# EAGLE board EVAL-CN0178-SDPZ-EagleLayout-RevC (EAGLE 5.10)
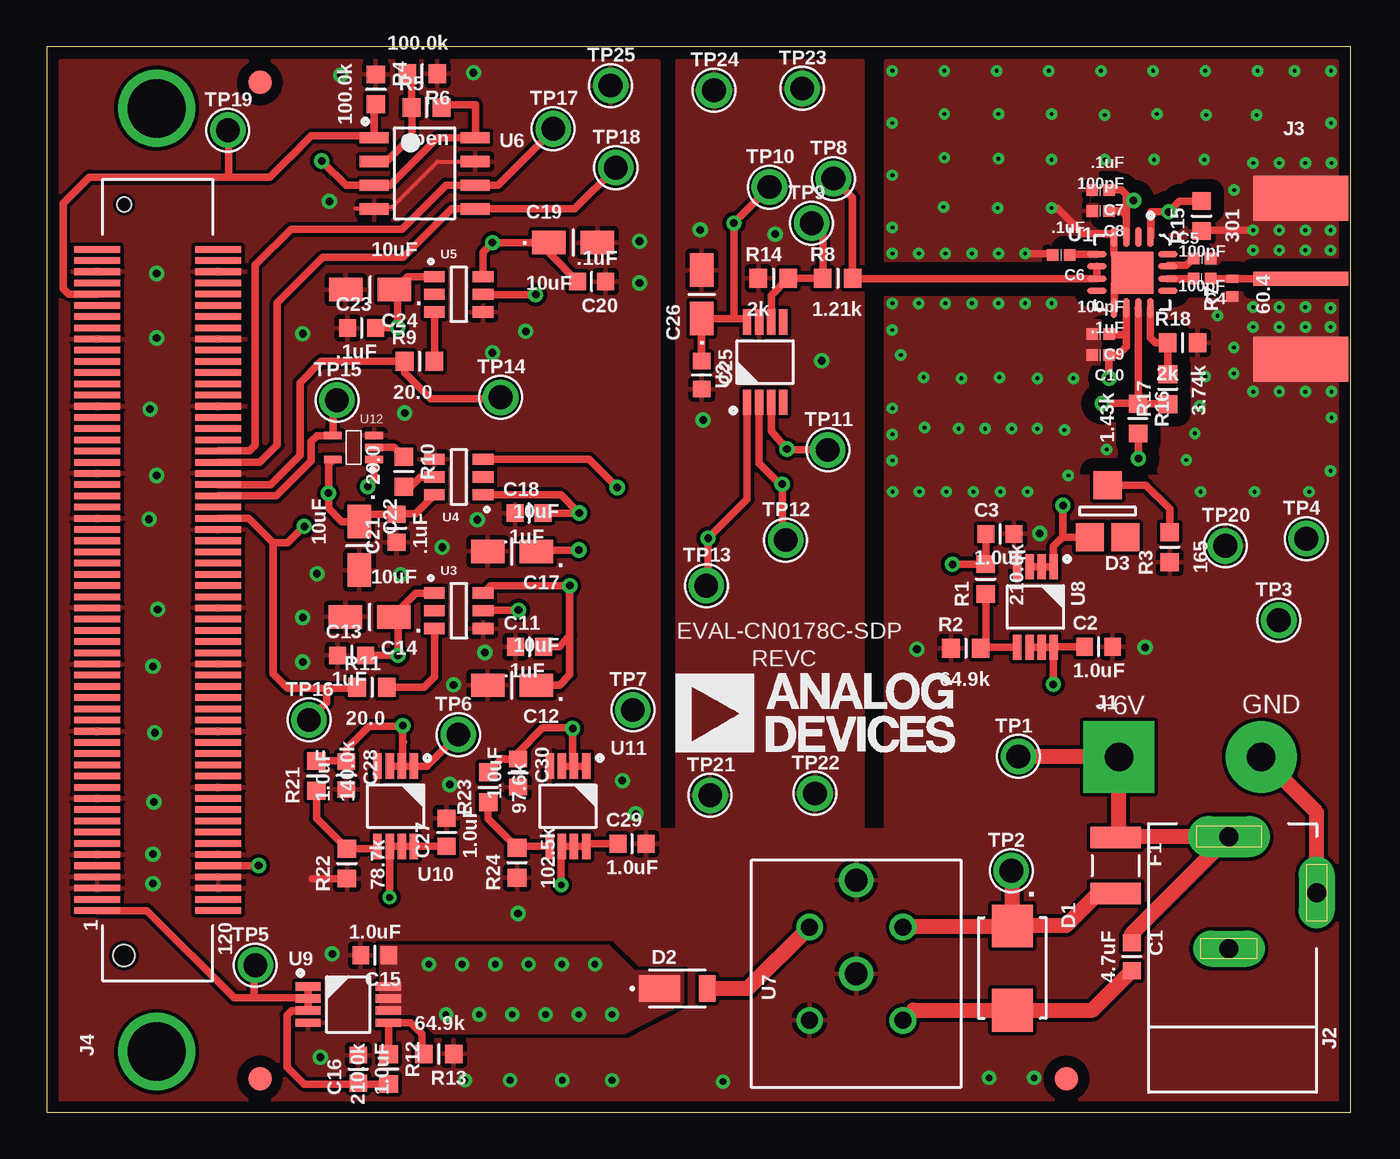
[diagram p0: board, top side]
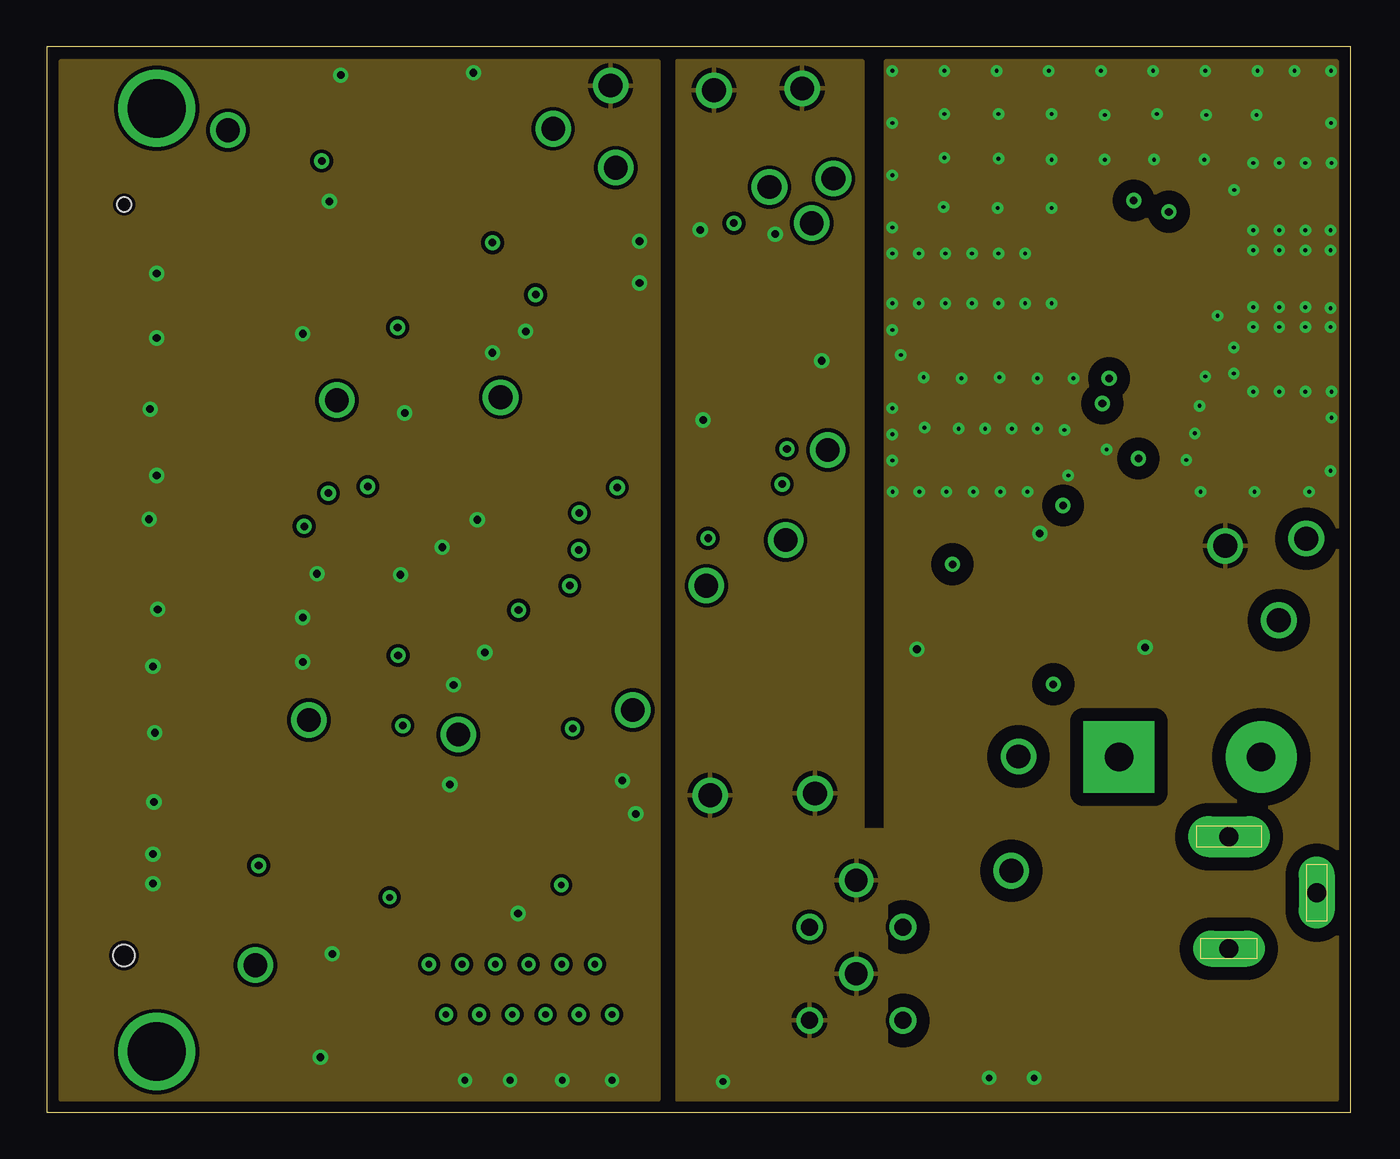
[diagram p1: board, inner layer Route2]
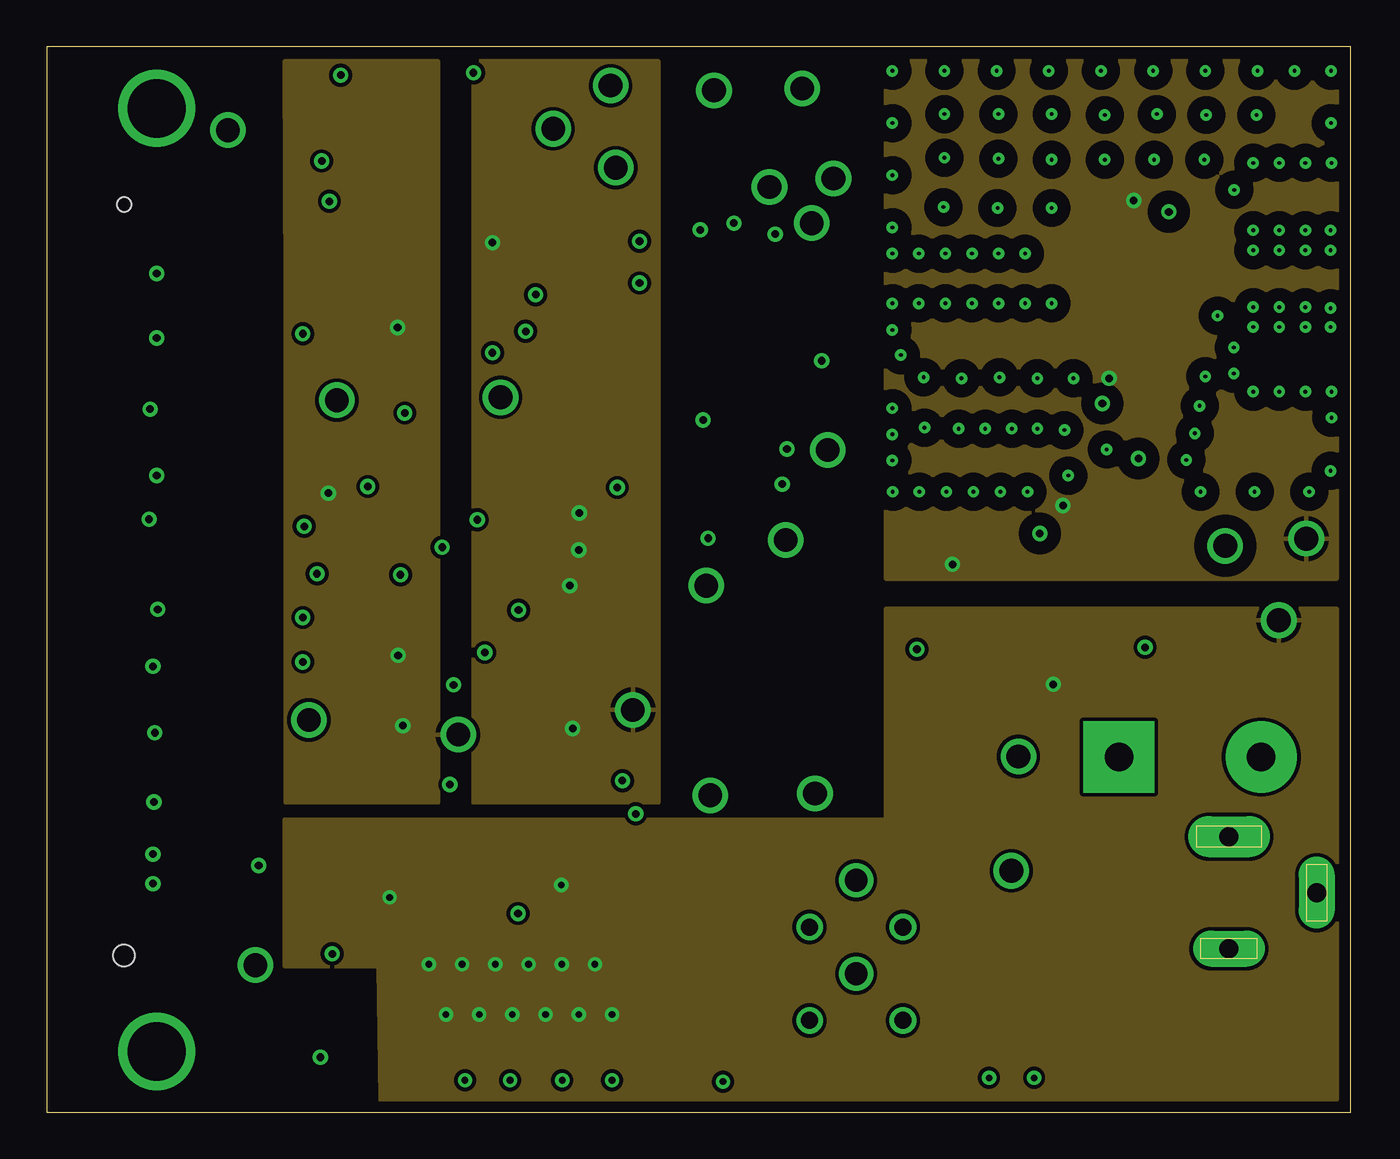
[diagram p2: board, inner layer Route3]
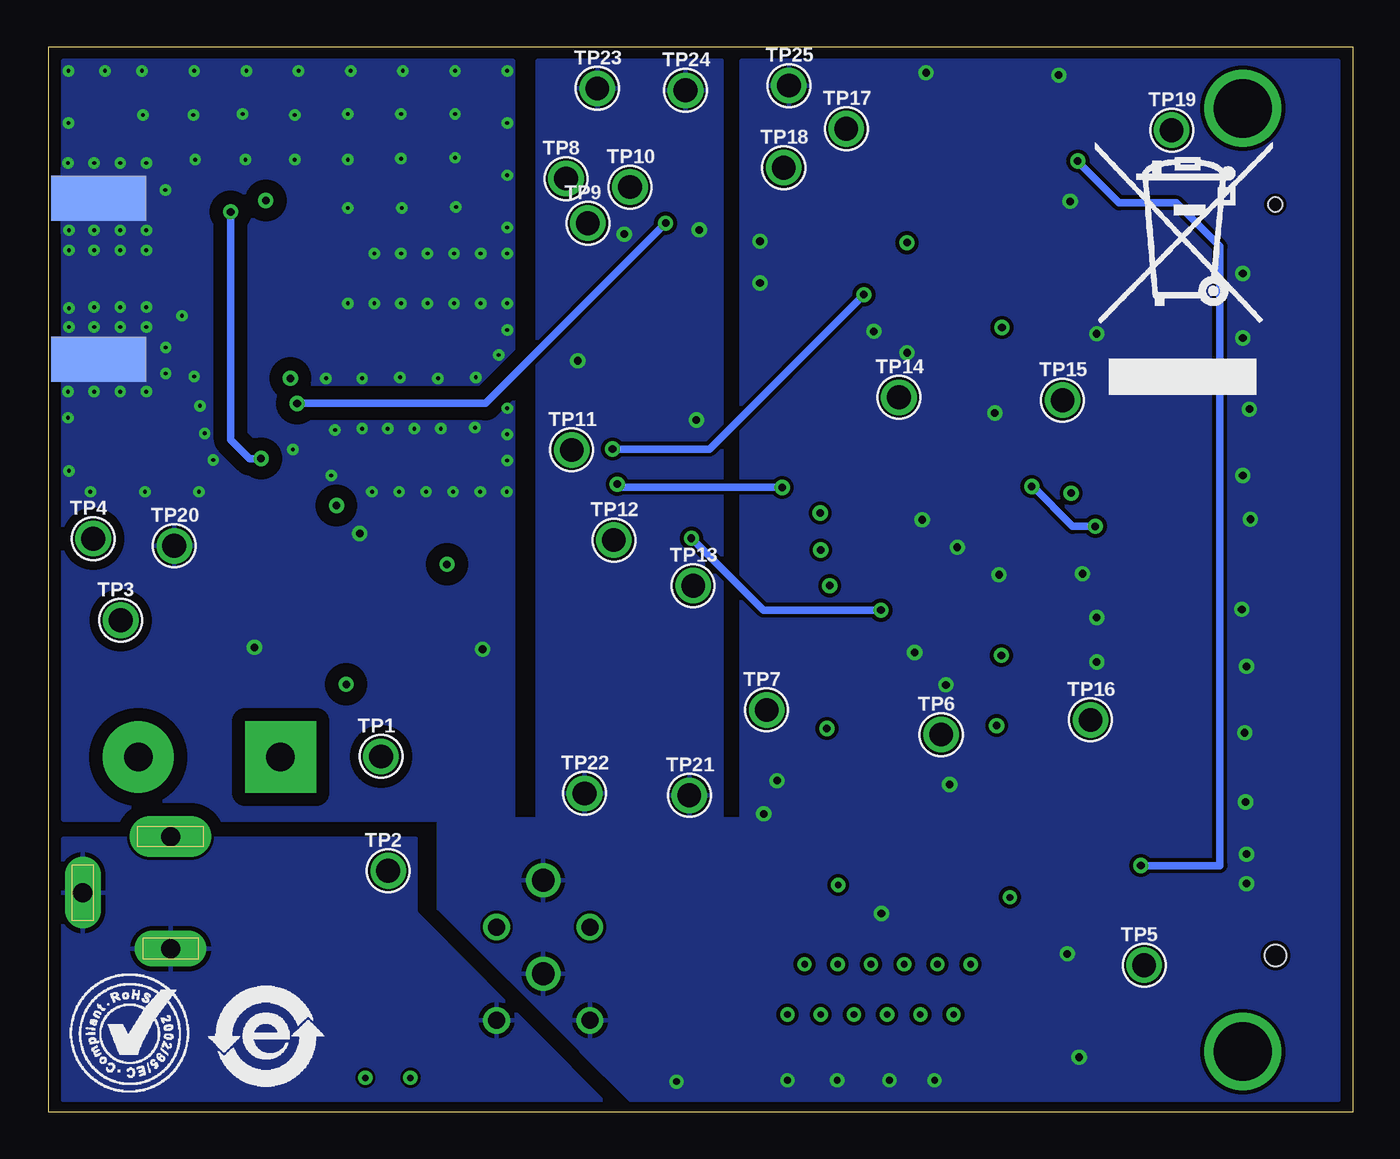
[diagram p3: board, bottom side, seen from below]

Size 69.85 x 57.05 mm. Coordinates in mm from the lower left corner, seen from the top.
Outline: 0,0 69.85,0 69.85,57.05 0,57.05 0,0
Copper layers (1+2*3+16): Top 0.035mm / dielectric 0.36mm / Route2 0.035mm / dielectric 0.71mm / Route3 0.035mm / dielectric 0.36mm / Bottom 0.035mm
Design rules "default *": minimum track width 5mil, minimum drill 8mil, track to track 6mil, track to pad 6mil, pad to pad 6mil, via to via 6mil, smd to smd 6mil, copper to edge 0mil, drill to drill 8mil, minimum pad ring 10mil, minimum via ring 8mil, stop-mask expansion 2mil, vias tented up to drill 0mil, thermal gap 10mil

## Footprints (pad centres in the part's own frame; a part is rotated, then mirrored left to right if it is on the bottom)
C_CAPC1608X55N = smd 0.9 x 0.95: 1 -0.75,0; 2 0.75,0
C_CAPC1005X55N = smd 0.62 x 0.62: 1 -0.45,0; 2 0.45,0
C_CAPMP3216X180N = smd 1.8 x 1.25: 1 -1.3,0; 2 1.3,0
D_DIOM5436X241N = smd 2.3 x 2.2: A 2.25,0; K -2.25,0
D_POWER123 = smd 0.9 x 1.4: A 1.6,0 | smd 2.2 x 1.4: K -0.95,0
D_LED_LUMEX_SMD = smd 1.5 x 1.5: 1 -0.95,1.4; 2 0.95,1.4; 3 0,-1.4
C_CAPC3225X94N = smd 1.15 x 2.7: 1 -1.5,0; 2 1.5,0
ID_PICKNPLACE = smd 1.27 x 1.27: P$1 0,0
CON_HEADER_2PIN = drill 1.524 pad 3.81 square: 1 -3.81,0 | drill 1.524 pad 3.81 round: 2 3.81,0
CON_BARREL_JACK = drill 1.016 pad 2.184 long: 1 -3,0 | drill 1.016 pad 1.93 long: 2 3,0; 3 0,4.7
CON_COAX_SMD = smd 2.413 x 5.08: PAD1 -4.318,-2.54; PAD2 4.318,-2.54 | smd 2.413 x 5.08 bottom: PAD3 -4.318,-2.54; PAD4 4.318,-2.54 | smd 0.762 x 5.08: SIG 0,-2.54
CON_120PIN_SMD = smd 0.35 x 2.46: 1 -17.7,3.23; 2 -17.1,3.23; 3 -16.5,3.23; 4 -15.9,3.23; 5 -15.3,3.23; 6 -14.7,3.23; 7 -14.1,3.23; 8 -13.5,3.23; 9 -12.9,3.23; 10 -12.3,3.23; 11 -11.7,3.23; 12 -11.1,3.23; 13 -10.5,3.23; 14 -9.9,3.23; 15 -9.3,3.23; 16 -8.7,3.23; 17 -8.1,3.23; 18 -7.5,3.23; 19 -6.9,3.23; 20 -6.3,3.23; 21 -5.7,3.23; 22 -5.1,3.23; 23 -4.5,3.23; 24 -3.9,3.23; 25 -3.3,3.23; 26 -2.7,3.23; 27 -2.1,3.23; 28 -1.5,3.23; 29 -0.9,3.23; 30 -0.3,3.23; 31 0.3,3.23; 32 0.9,3.23; 33 1.5,3.23; 34 2.1,3.23; 35 2.7,3.23; 36 3.3,3.23; 37 3.9,3.23; 38 4.5,3.23; 39 5.1,3.23; 40 5.7,3.23; 41 6.3,3.23; 42 6.9,3.23; 43 7.5,3.23; 44 8.1,3.23; 45 8.7,3.23; 46 9.3,3.23; 47 9.9,3.23; 48 10.5,3.23; 49 11.1,3.23; 50 11.7,3.23; 51 12.3,3.23; 52 12.9,3.23; 53 13.5,3.23; 54 14.1,3.23; 55 14.7,3.23; 56 15.3,3.23; 57 15.9,3.23; 58 16.5,3.23; 59 17.1,3.23; 60 17.7,3.23; 61 17.7,-3.23; 62 17.1,-3.23; 63 16.5,-3.23; 64 15.9,-3.23; 65 15.3,-3.23; 66 14.7,-3.23; 67 14.1,-3.23; 68 13.5,-3.23; 69 12.9,-3.23; 70 12.3,-3.23; 71 11.7,-3.23; 72 11.1,-3.23; 73 10.5,-3.23; 74 9.9,-3.23; 75 9.3,-3.23; 76 8.7,-3.23; 77 8.1,-3.23; 78 7.5,-3.23; 79 6.9,-3.23; 80 6.3,-3.23; 81 5.7,-3.23; 82 5.1,-3.23; 83 4.5,-3.23; 84 3.9,-3.23; 85 3.3,-3.23; 86 2.7,-3.23; 87 2.1,-3.23; 88 1.5,-3.23; 89 0.9,-3.23; 90 0.3,-3.23; 91 -0.3,-3.23; 92 -0.9,-3.23; 93 -1.5,-3.23; 94 -2.1,-3.23; 95 -2.7,-3.23; 96 -3.3,-3.23; 97 -3.9,-3.23; 98 -4.5,-3.23; 99 -5.1,-3.23; 100 -5.7,-3.23; 101 -6.3,-3.23; 102 -6.9,-3.23; 103 -7.5,-3.23; 104 -8.1,-3.23; 105 -8.7,-3.23; 106 -9.3,-3.23; 107 -9.9,-3.23; 108 -10.5,-3.23; 109 -11.1,-3.23; 110 -11.7,-3.23; 111 -12.3,-3.23; 112 -12.9,-3.23; 113 -13.5,-3.23; 114 -14.1,-3.23; 115 -14.7,-3.23; 116 -15.3,-3.23; 117 -15.9,-3.23; 118 -16.5,-3.23; 119 -17.1,-3.23; 120 -17.7,-3.23 | drill 3.124 round: MH1 -25.25,0.05; MH2 25.25,0.05 | hole 0.762: 20.1,1.8 | hole 1.168: -20.1,1.8
R_RESC1608X50AN = smd 0.95 x 1: 1 -0.8,0; 2 0.8,0
R_RESC1005X40N_RF = smd 0.57 x 0.62: 1 -0.48,0 | smd 0.406 x 0.62: 2 0.48,0
TP_50MIL = drill 1.27 round: 1 0,0
IC_QFN65P400X400X100-17VN = smd 1.05 x 0.35: 1 -1.9,0.975; 2 -1.9,0.325; 3 -1.9,-0.325; 4 -1.9,-0.975; 9 1.9,-0.975; 10 1.9,-0.325; 11 1.9,0.325; 12 1.9,0.975 | smd 0.35 x 1.05: 5 -0.975,-1.9; 6 -0.325,-1.9; 7 0.325,-1.9; 8 0.975,-1.9; 13 0.975,1.9; 14 0.325,1.9; 15 -0.325,1.9; 16 -0.975,1.9 | smd 2.25 x 2.25: 17 0,0
IC_SOP65P490X94-8N = smd 1.35 x 0.45: 1 -2.15,0.975; 2 -2.15,0.325; 3 -2.15,-0.325; 4 -2.15,-0.975; 5 2.15,-0.975; 6 2.15,-0.325; 7 2.15,0.325; 8 2.15,0.975
IC_SOT95P280X145-6AN = smd 1.1 x 0.6: 1 -1.3,0.95; 2 -1.3,0; 3 -1.3,-0.95; 4 1.3,-0.95; 5 1.3,0; 6 1.3,0.95
IC_SOIC127P600X175-8N = smd 1.55 x 0.6: 1 -2.7,1.905; 2 -2.7,0.635; 3 -2.7,-0.635; 4 -2.7,-1.905; 5 2.7,-1.905; 6 2.7,-0.635; 7 2.7,0.635; 8 2.7,1.905
IC_BNX016-01 = drill 0.914 round: 1 2.5,-2.5; 2 2.5,2.5; 3 -2.5,-2.5; 4 -2.5,2.5 | drill 1.219 round: 5 0,0; 6 5,0
IC_SOT65P210X110-5N = smd 0.95 x 0.4: 1 -1.1,0.65; 2 -1.1,0; 3 -1.1,-0.65; 4 1.1,-0.65; 5 1.1,0.65

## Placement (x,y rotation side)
C1  4.7uF  [C_CAPC1608X55N]  58.12,8.33 270 top
C2  1.0uF  [C_CAPC1608X55N]  56.34,24.92 0 top
C3  1.0uF  [C_CAPC1608X55N]  51.05,30.96 0 top
C4  100pF  [C_CAPC1005X55N]  61.87,44.63 180 top
C5  100pF  [C_CAPC1005X55N]  61.87,45.72 0 top
C6  .1uF  [C_CAPC1005X55N]  54.33,45.9 180 top
C7  .1uF  [C_CAPC1005X55N]  56.44,49.38 180 top
C8  100pF  [C_CAPC1005X55N]  56.44,48.26 180 top
C9  100pF  [C_CAPC1005X55N]  56.44,41.66 180 top
C10  .1uF  [C_CAPC1005X55N]  56.44,40.54 180 top
C11  .1uF  [C_CAPC1608X55N]  25.86,24.92 0 top
C12  10uF  [C_CAPMP3216X180N]  24.92,22.86 180 top
C13  .1uF  [C_CAPC1608X55N]  16.33,24.46 0 top
C14  10uF  [C_CAPMP3216X180N]  17.3,26.52 180 top
C15  1.0uF  [C_CAPC1608X55N]  17.58,8.41 180 top
C16  1.0uF  [C_CAPC1608X55N]  16.69,2.31 90 top
C17  10uF  [C_CAPMP3216X180N]  24.92,30.02 180 top
C18  .1uF  [C_CAPC1608X55N]  25.83,32.08 0 top
C19  10uF  [C_CAPMP3216X180N]  28.19,46.56 0 top
C20  .1uF  [C_CAPC1608X55N]  29.18,44.48 180 top
C21  .1uF  [C_CAPC1608X55N]  18.75,31.27 90 top
C22  10uF  [C_CAPMP3216X180N]  16.74,30.33 270 top
C23  .1uF  [C_CAPC1608X55N]  16.87,41.99 0 top
C24  10uF  [C_CAPMP3216X180N]  17.32,44.04 180 top
C25  [C_CAPC1608X55N]  35.08,39.47 270 top
C26  10uF  [C_CAPMP3216X180N]  35.08,43.79 90 top
C27  1.0uF  [C_CAPC1608X55N]  21.41,14.99 90 top
C28  1.0uF  [C_CAPC1608X55N]  16.05,18.03 270 top
C29  1.0uF  [C_CAPC1608X55N]  31.34,14.38 0 top
C30  1.0uF  [C_CAPC1608X55N]  25.25,18.16 270 top
D1  [D_DIOM5436X241N]  51.71,7.72 270 top
D2  [D_POWER123]  33.78,6.63 0 top
D3  [D_LED_LUMEX_SMD]  56.82,32.18 180 top
DRILEGEND  [DRILEGEND]  not placed on the board
F1  [C_CAPC3225X94N]  57.25,13.21 270 top
ID1  INDICATOR  [ID_PICKNPLACE]  11.43,55.14 0 top
ID2  INDICATOR  [ID_PICKNPLACE]  54.61,1.8 0 top
ID3  INDICATOR  [ID_PICKNPLACE]  11.43,1.8 0 top
J1  CON_HEADER_2PIN  [CON_HEADER_2PIN]  61.24,19.02 0 top
J2  [CON_BARREL_JACK]  63.32,11.76 270 top
J3  [CON_COAX_SMD]  64.62,44.63 90 top
J4  [CON_120PIN_SMD]  5.94,28.5 90 top
R1  210.0k  [R_RESC1608X50AN]  50.29,28.55 90 top
R2  64.9k  [R_RESC1608X50AN]  49.23,24.84 0 top
R3  165  [R_RESC1608X50AN]  60.15,30.25 90 top
R4  100.0k  [R_RESC1608X50AN]  17.63,54.76 270 top
R5  open  [R_RESC1608X50AN]  20.35,53.8 0 top
R6  100.0k  [R_RESC1608X50AN]  20.12,55.6 180 top
R7  60.4  [R_RESC1005X40N_RF]  63.5,44.15 90 top
R8  1.21k  [R_RESC1608X50AN]  42.37,44.65 0 top
R9  20.0  [R_RESC1608X50AN]  19.96,40.21 0 top
R10  20.0  [R_RESC1608X50AN]  19.13,34.29 270 top
R11  20.0  [R_RESC1608X50AN]  17.42,22.76 0 top
R12  210.0k  [R_RESC1608X50AN]  18.31,2.31 270 top
R13  64.9k  [R_RESC1608X50AN]  21.01,3.12 180 top
R14  2k  [R_RESC1608X50AN]  38.91,44.65 0 top
R15  301  [R_RESC1608X50AN]  61.85,47.98 90 top
R16  1.43k  [R_RESC1608X50AN]  58.45,37.13 270 top
R17  3.74k  [R_RESC1608X50AN]  60.05,38.71 90 top
R18  2k  [R_RESC1608X50AN]  60.83,41.2 0 top
R21  140.0k  [R_RESC1608X50AN]  14.45,18.01 90 top
R22  78.7k  [R_RESC1608X50AN]  16.08,13.31 90 top
R23  97.6k  [R_RESC1608X50AN]  23.65,17.4 90 top
R24  102.5k  [R_RESC1608X50AN]  25.2,13.36 90 top
TP1  TESTPOINT_50MIL  [TP_50MIL]  52.04,19.05 0 top
TP2  TESTPOINT_50MIL  [TP_50MIL]  51.66,12.93 0 top
TP3  TESTPOINT_50MIL  [TP_50MIL]  65.99,26.34 0 top
TP4  TESTPOINT_50MIL  [TP_50MIL]  67.46,30.71 0 top
TP5  TESTPOINT_50MIL  [TP_50MIL]  11.18,7.87 0 top
TP6  TESTPOINT_50MIL  [TP_50MIL]  22.05,20.22 0 top
TP7  TESTPOINT_50MIL  [TP_50MIL]  31.39,21.54 0 top
TP8  TESTPOINT_50MIL  [TP_50MIL]  42.14,49.99 0 top
TP9  TESTPOINT_50MIL  [TP_50MIL]  40.97,47.6 0 top
TP10  TESTPOINT_50MIL  [TP_50MIL]  38.71,49.53 0 top
TP11  TESTPOINT_50MIL  [TP_50MIL]  41.83,35.46 0 top
TP12  TESTPOINT_50MIL  [TP_50MIL]  39.57,30.63 0 top
TP13  TESTPOINT_50MIL  [TP_50MIL]  35.33,28.19 0 top
TP14  TESTPOINT_50MIL  [TP_50MIL]  24.31,38.28 0 top
TP15  TESTPOINT_50MIL  [TP_50MIL]  15.54,38.13 0 top
TP16  TESTPOINT_50MIL  [TP_50MIL]  14.05,21.01 0 top
TP17  TESTPOINT_50MIL  [TP_50MIL]  27.13,52.65 0 top
TP18  TESTPOINT_50MIL  [TP_50MIL]  30.48,50.57 0 top
TP19  TESTPOINT_50MIL  [TP_50MIL]  9.7,52.58 0 top
TP20  TESTPOINT_50MIL  [TP_50MIL]  63.12,30.33 0 top
TP21  TESTPOINT_50MIL  [TP_50MIL]  35.53,16.97 0 top
TP22  TESTPOINT_50MIL  [TP_50MIL]  41.15,17.07 0 top
TP23  TESTPOINT_50MIL  [TP_50MIL]  40.46,54.81 0 top
TP24  TESTPOINT_50MIL  [TP_50MIL]  35.74,54.71 0 top
TP25  TESTPOINT_50MIL  [TP_50MIL]  30.2,54.97 0 top
U1  IC_ADL5902_LFCSP_VQ  [IC_QFN65P400X400X100-17VN]  58.14,44.96 270 top
U2  IC_AD7466_TSSOP8  [IC_SOP65P490X94-8N]  38.48,40.16 90 top
U3  [IC_SOT95P280X145-6AN]  22.07,26.85 0 top
U4  [IC_SOT95P280X145-6AN]  22.07,34.01 180 top
U5  [IC_SOT95P280X145-6AN]  22.07,43.79 0 top
U6  [IC_SOIC127P600X175-8N]  20.24,50.27 0 top
U7  [IC_BNX016-01]  43.36,7.42 90 top
U8  [IC_SOP65P490X94-8N]  52.96,27.05 270 top
U9  [IC_SOP65P490X94-8N]  16.15,5.77 0 top
U10  [IC_SOP65P490X94-8N]  18.69,16.38 270 top
U11  [IC_SOP65P490X94-8N]  27.91,16.38 270 top
U12  IC_74HC_HCT1G125  [IC_SOT65P210X110-5N]  16.43,35.59 180 top
U$11  [LOGO_ANALOG_DEVICES]  33.68,19.25 0 top
U$12  [LOGO_ROHS]  68.83,1.07 0 bottom
U$13  [LOGO_ROHS_CHINA]  61.52,1.37 0 bottom
U$14  [LOGO_WEEE_TRASH]  13.82,38.4 0 bottom

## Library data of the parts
C1-C25 C27-C30 D1-D3 F1 J1-J4 R1-R18 R21-R24 TP1-TP25 U1-U12 = CN-0178-RevC
C26 = CN-0178-RevB
DRILEGEND = drilegend
ID1-ID3 = CN0150
U$11-U$14 = Templates

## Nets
+2.3V: C11.2 C12.1 C17.1 C18.2 C19.1 C20.2 C30.1 R23.2 TP7.1 U3.6 U4.1 U5.6 U11.1 U11.2 U11.3
+3.3V: C13.2 C14.1 C21.2 C22.1 C23.2 C24.1 C28.1 R21.2 TP6.1 U3.1 U4.6 U5.1 U10.1 U10.2 U10.3 U12.5
+3.3V_EEPROM: J4.116 R5.2 U6.3 U6.8
+5V_ANALOG: C3.1 C7.1 C8.1 C9.1 C10.1 D3.2 R1.2 TP4.1 U1.3 U1.10 U8.1 U8.2 U8.3
+5V_SDP: C16.1 J4.1 R12.2 TP5.1 U9.1 U9.2 U9.3
GND: C2.2 C3.2 C5.2 C6.2 C7.2 C8.2 C9.2 C10.2 C11.1 C12.2 C13.1 C14.2 C15.2 C16.2 C17.2 C18.1 C19.2 C20.1 C21.1 C22.2 C23.1 C24.2 C25.2 C26.2 C27.2 C28.2 C29.2 C30.2 J3.PAD1 J3.PAD2 J3.PAD3 J3.PAD4 J4.3 J4.4 J4.6 J4.11 J4.17 J4.23 J4.28 J4.36 J4.40 J4.46 J4.52 J4.58 J4.63 J4.69 J4.75 J4.81 J4.86 J4.93 J4.98 J4.104 J4.109 J4.115 J4.117 J4.118 R2.1 R3.1 R4.1 R6.1 R7.1 R13.1 R14.1 R15.1 R18.2 R22.1 R24.1 TP20.1 TP21.1 TP22.1 TP23.1 TP24.1 TP25.1 U1.4 U1.9 U1.17 U2.7 U3.4 U4.4 U5.4 U6.4 U6.7 U7.4 U7.5 U7.6 U8.4 U9.4 U10.4 U11.4 U12.3
N$1: C6.1 U1.5
N$2: C5.1 U1.15
N$3: C4.2 U1.14
N$4: R17.2 R18.1 U1.12
N$5: C4.1 J3.SIG R7.2
N$6: J4.56 R4.2 TP19.1 U6.1
N$7: TP13.1 U2.1 U3.5
N$8: R15.2 R16.2 U1.1
N$9: R5.1 R6.2 U6.2
N$10: R8.1 R14.2 TP9.1 U2.6
N$11: R8.2 TP8.1 U1.6 U1.7
N$12: R10.1 U12.2
N$13: TP12.1 U2.2 U4.3
N$14: R1.1 R2.2 U8.5
N$15: D1.K F1.2 TP2.1 U7.1
N$16: D2.A U7.2
N$17: TP11.1 U2.3 U5.5
N$18: D3.3 R3.2
N$19: R12.1 R13.2 U9.5
N$20: R9.2 U5.3
N$21: R21.1 R22.2 U10.5
N$22: R23.1 R24.2 U11.5
N$23: R10.2 U4.5
N$24: R11.2 U3.3
N$27: C25.1 C26.1 R16.1 R17.1 TP10.1 U1.11 U2.8
PGND: C1.2 D1.A J1.2 J2.2 J2.3 U7.3
SCL_0: J4.79 TP17.1 U6.6
SDA_0: J4.80 TP18.1 U6.5
SPI_CLK: J4.82 R9.1 TP14.1
SPI_MISO: J4.83 TP15.1 U12.4
SPI_SEL_A: J4.85 R11.1 TP16.1 U12.1
VIN2: C2.1 C15.1 C27.1 C29.1 D2.K TP3.1 U8.6 U8.7 U8.8 U9.6 U9.7 U9.8 U10.6 U10.7 U10.8 U11.6 U11.7 U11.8
VIN_JACK: C1.1 F1.1 J1.1 J2.1 TP1.1

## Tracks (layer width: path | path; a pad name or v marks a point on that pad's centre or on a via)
+2.3V  (via drill 0.41)
  Top 0.406: 28.02,25.55 27.46,24.92 C11.2 | 28.02,25.55 28.02,23.42 27.46,22.86 C12.1 | 28.02,25.55 v28.02,28.19 23.77,28.19 U3.6 | U5.6 23.37,46.05 v23.88,46.56 C19.1 26.89,46.36 26.92,46.33 26.92,45.99 C20.2 | U4.1 27.54,33.06 v28.52,32.08 C18.2 | U11.2 U11.3 | U11.2 28.17,18.6 v28.17,20.55 28.14,20.57 26.57,20.57 25.25,19.25 C30.1 24.55,18.91 24.54,18.92 24.37,18.92 R23.2 | U11.2 U11.1 | C17.1 26.29,30.1 v28.5,30.1
  pour Route3 (isolate 0.203): 22.86,56.29 32.77,56.29 32.77,16.56 22.86,16.56
+3.3V  (via drill 0.41)
  Top 0.127: U3.1 20.77,27.79 20.76,27.79 | 19.07,18.56 19.07,18.53 U10.1 | C22.1 | C21.2 18.77,32.04
  Top 0.203: 19.07,19.94 19.2,19.81
  Top 0.406: v19.07,20.7 19.07,18.56 | 18.77,32.04 19.76,32.04 U4.6 | v19.07,20.7 19.1,20.68 | v19.07,20.7 19.05,20.68 17.27,20.68 16.05,19.46 C28.1 16.03,18.81 R21.2 | v19.07,20.7 19.07,19.94 | 20.76,27.79 19.76,27.79 18.82,26.85 18.82,26.52 | C22.1 15.8,31.62 15.09,32.33 v15.09,33.15 15.09,34.69 U12.5 | U5.1 19.32,44.74 C24.1 18.8,43.87 v18.8,42.01 17.64,42.01 C23.2 | U10.3 U10.2 U10.1 20.39,18.53 20.39,18.56 TP6.1 | C13.2 v18.82,24.46 18.82,26.52 | 18.82,26.52 C14.1 | C21.2 18.73,32 17.25,32 16.87,31.63 C22.1
  pour Route3 (isolate 0.203): 12.75,56.29 20.95,56.29 20.95,16.56 12.8,16.56 12.8,43.94
+3.3V_EEPROM  (via drill 0.41)
  Top 0.203: U6.8 22.94,52.37 22.94,52.79
  Top 0.406: U6.8 20.93,52.17 18.39,49.63 U6.3 16.03,49.63 v14.73,50.93 | 22.94,52.37 22.96,52.39 22.96,53.95 21.3,53.95 R5.2 | J4.116 9.18,13.21 v11.35,13.21
  Bottom 0.406: v11.35,13.21 7.11,13.21 7.11,46.36 9.45,48.69 12.52,48.69 14.73,50.9 v14.73,50.93
+5V_ANALOG  (via drill 0.41)
  Top 0.127: 54.43,30.76 54.45,30.78 54.56,30.78 | U1.10 | U8.1 53.93,29.21 53.92,29.21
  Top 0.406: 57.81,41.63 57.81,41 57.35,40.54 C10.1 v56.9,39.29 | 57.81,48.16 57.82,48 57.56,48.26 C8.1 | 57.81,48.16 57.81,48.87 | 57.81,48.87 v58.22,48.82 | 57.81,48.87 57.82,49.12 57.56,49.38 C7.1 | 53.92,29.21 53.92,30.3 54.4,30.78 54.56,30.78 D3.2 | 54.43,30.76 v54.43,32.49 | U1.3 57.81,48.16 | U8.3 U8.2 U8.1 | C3.1 R1.2 v48.51,29.34 | C9.1 56.91,41.63 57.81,41.63 | U1.10 57.81,41.63
  pour Route3 (isolate 0.711): 44.96,56.29 69.09,56.29 69.09,28.55 44.96,28.55
+5V_SDP
  Top 0.127: 13.97,6.12 U9.2 | 16.64,1.51 C16.1 | 11.12,7.9 11.15,7.87 TP5.1
  Top 0.406: 11.12,6.12 10.03,6.12 5.36,10.8 J4.1 | 11.12,6.12 13.97,6.12 | 16.64,1.51 13.78,1.51 12.88,2.41 12.88,5.21 13.11,5.44 U9.3 U9.2 U9.1 | 11.12,6.12 11.12,7.9 | C16.1 16.74,1.51 R12.2
GND  (via drill 0.2, 0.36, 0.41)
  Top 0.203: 16.55,48.38 U6.4 18.09,48.49 18.52,48.49 20.93,50.9 U6.7
  Top 0.406: v53.82,48.41 54.13,48.41 55.5,47.04 56.98,47.04 U1.4 57.17,45.93 U1.17 57.81,44.96 57.17,44.32 U1.9 | R15.1 61.89,47.22 v64.62,47.22 | 14.21,12.51 R22.1 | C6.2 53.8,45.97 v52.4,45.97
  other vias: 22.4,1.71 15.29,8.48 68.81,50.83 15.75,55.52 22.86,55.65 15.14,48.77 31.75,46.63 31.75,44.4 13.72,41.68 21.18,30.25 18.95,28.78 14.48,28.83 13.72,26.49 21.59,17.55 30.84,17.75 35,47.24 39.01,47.02 35.15,37.06 46.61,24.79 58.83,24.89 14.66,2.95 5.89,44.91 5.89,41.45 5.54,37.64 5.89,34.09 5.49,31.75 5.94,26.92 5.69,23.88 5.79,20.32 5.74,16.61 5.69,13.82 5.69,12.24 53.19,30.99 24.82,1.71 27.61,1.71 30.28,1.71 50.47,1.84 52.88,1.84 36.22,1.64 41.5,40.23 25.25,10.64 31.55,15.98 13.72,24.1 23.47,24.61 21.79,22.89 67.41,50.83 66.01,50.83 64.62,50.83 66.01,47.22 67.41,47.22 68.76,47.22 68.76,46.15 67.41,46.15 66.01,46.15 64.62,46.15 64.62,43.1 66.01,43.1 67.41,43.1 68.76,43.05 45.29,43.31 46.71,43.31 48.13,43.31 49.56,43.31 50.98,43.31 52.4,43.31 53.82,43.31 50.98,45.97 49.56,45.97 48.13,45.97 46.71,45.97 45.29,45.97 64.62,42.04 66.01,42.04 67.41,42.04 68.76,42.04 45.29,41.88 45.75,40.54 45.29,37.69 45.29,36.3 45.29,34.9 46.74,33.22 48.18,33.22 49.63,33.22 51.08,33.22 52.53,33.22 54.51,36.53 68.81,38.58 67.41,38.58 66.01,38.58 64.62,38.58 63.58,39.55 63.58,40.94 62.71,42.65 68.81,37.19 68.76,34.34 67.61,33.22 64.69,33.22 61.8,33.22 45.29,47.37 45.29,50.16 45.29,52.96 45.29,55.75 48.08,55.75 50.88,55.75 53.67,55.75 56.46,55.75 59.26,55.75 62.05,55.75 64.85,55.75 66.83,55.75 68.78,55.75 68.78,52.96 63.6,49.38 61.75,37.82 62.05,39.4 46.96,39.34 49,39.29 51.03,39.34 53.06,39.29 54.99,39.29 47.02,36.65 48.84,36.6 50.27,36.6 51.69,36.6 53.06,36.6 56.77,35.48 48.03,48.46 50.93,48.41 48.08,51.1 50.98,51.05 53.82,51 56.67,51 59.31,51 62,51 45.31,33.22 61.04,34.93 61.49,36.35 54.71,34.09 48.08,53.44 50.98,53.44 53.82,53.44 56.67,53.39 59.46,53.44 62.1,53.39 64.8,53.39 23.06,31.72 23.88,40.67 25.65,41.81 19.18,37.44
  pour Top (isolate 0.711): 44.96,56.29 69.09,56.29 69.09,34.19 44.96,34.19
  pour Top (isolate 0.203, rank 2): 33.78,56.29 43.69,56.29 43.69,8.08 33.78,8.08
  pour Top (isolate 0.203, rank 2): 0.76,56.29 32.77,56.29 32.77,0.66 0.76,0.66
  pour Bottom (isolate 0.203): 33.78,56.29 43.69,56.29 43.69,15.7 33.78,15.7
  pour Bottom (isolate 0.711): 44.96,56.29 69.09,56.29 69.09,15.67 44.96,15.67
  pour Bottom (isolate 0.203): 12.7,56.29 32.77,56.29 32.77,0.66 12.7,0.66
  pour Top (isolate 0.711, no thermals): 63.25,56.29 69.09,56.29 69.09,46.76 63.25,46.76
  pour Top (isolate 0.203, rank 2): 12.95,0.66 0.76,0.66 0.76,56.29 12.95,56.29
  pour Top (isolate 0.711, no thermals): 62.64,42.37 69.09,42.37 69.09,36.73 62.64,36.73
  pour Bottom (no thermals): 63.4,41.96 69.09,41.96 69.09,37.69 63.45,37.69 63.45,41.91
  pour Bottom (isolate 0.203, no thermals): 63.8,50.6 63.8,47.04 69.09,47.04 69.09,50.6
  pour Top (isolate 0.203, rank 2): 30.38,15.14 50.8,15.14 50.8,0.66 30.35,0.66 30.35,8.15
  pour Route2 (isolate 0.711): 44.96,56.29 69.09,56.29 69.09,0.66 44.96,0.66
  pour Route2 (isolate 0.203): 33.78,56.29 43.69,56.29 43.69,0.66 33.78,0.66
  pour Route2 (isolate 0.203): 12.7,56.29 32.77,56.29 32.77,0.66 12.7,0.66
  pour Top (no thermals): 55.07,42.37 56.39,42.37 56.39,40.08 55.07,40.08
  pour Top (isolate 0.711): 55.12,49.68 56.34,49.68 56.34,47.6 55.12,47.6
  pour Top (isolate 0.356, no thermals): 62.99,43.84 64.01,43.84 64.01,43.03 62.99,43.03
  pour Route2 (isolate 0.203): 33.78,15.14 44.96,15.14 44.96,0.66 33.78,0.66
  pour Route2 (isolate 0.203): 12.95,0.66 0.76,0.66 0.76,56.29 12.95,56.29
  pour Bottom (isolate 0.203): 12.95,0.66 0.76,0.66 0.76,56.29 12.95,56.29
  pour Bottom: 32.82,15.7 48.97,15.7 48.97,10.92 41.35,3.35 41.35,3.3 38.71,0.66 32.77,0.66 32.77,15.6
  pour Top (isolate 0.203): 44.96,34.06 69.09,34.06 69.09,0.66 44.96,0.66
  pour Top (no thermals): 62.08,45.97 62.08,45.47 62.69,45.47 62.99,45.77 62.99,45.97
  pour Top (no thermals): 55.78,48.62 56.29,48.62 56.29,47.96 55.78,47.96 55.78,48.56
  pour Top: 55.52,50.04 56.29,50.5 56.29,49.07 55.52,49.07
N$1
  Top 0.127: U1.5 56.24,45.9 56.2,45.9
  Top 0.406: C6.1 54.82,45.93 U1.5
N$2
  Top 0.127: U1.15 60.04,45.34 60.1,45.34
  Top 0.406: 60.1,45.34 61.04,45.34 C5.1
N$3
  Top 0.406: U1.14 C4.2
N$4
  Top 0.127: 59.11,43.05 59.11,43.06 U1.12
  Top 0.406: 59.11,43.05 59.11,41.48 59.38,41.2 R18.1 60.05,41.19 R17.2
N$5
  Top 0.406: J3.SIG R7.2 C4.1
N$6
  Top 0.203: 13.02,51.14 13.04,51.14 | 14.17,52.27 14.28,52.27 | 17.44,52.27 U6.1 17.63,52.26
  Top 0.406: 9.78,50.06 2.29,50.06 0.89,48.67 0.89,44.09 1.19,43.8 J4.56 | 9.78,50.06 11.94,50.06 13.02,51.14 | 13.04,51.14 14.17,52.27 | 14.28,52.27 17.44,52.27 | 9.78,50.06 9.75,50.09 9.75,52.53 TP19.1 | J4.56 | R4.2 17.54,53.88 U6.1
N$7  (via drill 0.41)
  Top 0.406: 25.24,26.85 v25.27,26.88 23.41,26.88 U3.5 | U2.1 37.51,32.82 v35.42,30.73 35.42,28.29 TP13.1
  Bottom 0.406: v25.27,26.88 31.57,26.88 v35.42,30.73
N$8  (via drill 0.41)
  Top 0.127: U1.1 59.12,46.87 59.13,46.87 | 58.47,36.33 R16.2
  Top 0.406: v58.47,35 58.47,36.33 | R15.2 60.67,48.78 v60.1,48.21 59.13,48.21 59.13,46.87 59.14,46.86
  Bottom 0.406: v58.47,35 59.08,35 60.1,36.02 v60.1,48.21
N$9
  Top 0.406: R6.2 19.55,55.37 R5.1 19.56,53.78 19.56,52.27 18.19,50.9 U6.2
N$10
  Top 0.406: U2.6 38.81,43.75 R14.2 R8.1 41.57,47 TP9.1
N$11
  Top 0.406: U1.6 U1.7 43.19,44.63 R8.2 43.17,48.96 TP8.1
N$12
  Top 0.406: U12.2 17.55,35.6 18.62,35.6 R10.1
N$13  (via drill 0.41)
  Top 0.127: U2.2
  Top 0.406: v30.56,33.45 29.05,34.96 U4.3 | U2.2 38.15,34.75 39.27,33.63 v39.4,33.63 39.4,30.81 TP12.1
  Bottom 0.406: v30.56,33.45 39.22,33.45 v39.4,33.63
N$14
  Top 0.127: 51.92,24.84 51.92,24.9 U8.5
  Top 0.406: R2.2 50.29,25.11 | 50.29,25.11 R1.1 | 50.29,25.11 50.5,24.9 U8.5
N$15
  Top 0.813: U7.1 45.91,9.97 D1.K | D1.K 51.75,10.01 54.61,10.01 56.36,11.76 56.46,11.76 56.52,11.71 F1.2 | TP2.1 51.71,12.88 D1.K
N$16
  Top 0.813: U7.2 37.57,6.63 D2.A
N$17  (via drill 0.41)
  Top 0.127: U5.5 23.37,43.77 23.6,43.77
  Top 0.406: 23.39,43.77 23.6,43.77 v26.19,43.77 | U2.3 38.81,36.45 v39.65,35.51 39.7,35.46 TP11.1
  Bottom 0.406: v39.65,35.51 34.45,35.51 v26.19,43.77
N$18
  Top 0.406: R3.2 60.15,32.31 58.87,33.58 D3.3
N$19
  Top 0.127: 20.12,3.19 20.18,3.12 R13.2
  Top 0.406: 20.12,3.19 20.12,4.17 19.49,4.79 U9.5 18.3,3.12 R12.1
N$20
  Top 0.406: R9.2 20.77,40.22 U5.3
N$21
  Top 0.127: U10.5 17.75,14.2 17.75,14.11
  Top 0.406: U10.5 17.6,14.11 R22.2 14.45,15.74 R21.1
N$22
  Top 0.406: 25.25,14.23 24.93,14.23 | 25.25,14.23 U11.5 | R23.1 23.65,15.71 R24.2 25.25,14.21 25.25,14.23
N$23
  Top 0.127: U4.5 20.77,33.99 20.37,33.99
  Top 0.406: 20.75,33.99 20.37,33.99 19.99,33.99 19.5,33.49 R10.2
N$24
  Top 0.127: U3.3
  Top 0.406: U3.3 20.78,23.32 20.22,22.76 R11.2
N$27  (via drill 0.41)
  Top 0.127: 37.32,42.49 U2.8 | 58.43,37.95 R16.1
  Top 0.406: 36.8,42.49 37.32,42.49 | 36.8,42.49 C26.1 C25.1 | 36.8,42.49 v36.8,47.6 36.8,47.63 TP10.1 | v56.54,37.95 58.43,37.95 58.47,37.98 U1.11 58.45,43.04 | R17.1 60.02,37.93 R16.1
  Bottom 0.406: v56.54,37.95 46.46,37.95 v36.8,47.6
PGND
  Top 0.813: J1.2 68.02,16.05 68.02,15.82 J2.3 | U7.3 46.41,5.47 D1.A 56.01,5.47 C1.2
  pour Bottom: 40.23,0.66 50.16,10.69 50.16,14.63 69.09,14.63 69.09,0.66
SCL_0
  Top 0.127: 9.19,35.41 9.19,35.4 J4.79
  Top 0.406: 9.19,35.41 10.87,35.41 11.18,35.71 11.18,45.36 13.08,47.27 19.02,47.27 21.39,49.63 U6.6 24.18,49.63 27.13,52.58 TP17.1
SDA_0
  Top 0.127: J4.80 | J4.80
  Top 0.406: J4.80 11.4,34.8 12.32,35.71 12.34,35.71 12.34,43.33 14.78,45.77 19.1,45.77 21.69,48.36 U6.5 28.27,48.36 TP18.1
SPI_CLK
  Top 0.127: TP14.1 24.33,38.25 24.33,38.2
  Top 0.203: 13.56,35.66 13.59,35.69
  Top 0.406: 24.33,38.2 20.55,38.2 19.16,39.59 R9.1 14.71,40.21 13.56,39.07 13.56,35.66 13.56,35.17 11.99,33.6 J4.82 | J4.82
SPI_MISO
  Top 0.406: J4.83 | J4.83 12.3,33 14.17,34.87 14.17,35.92 14.48,36.22 15.32,36.22 U12.4 15.33,37.91 TP15.1
SPI_SEL_A  (via drill 0.41)
  Top 0.127: 16.41,22.71 16.46,22.76 | 9.18,31.8 J4.85 | 16.57,22.71 R11.1
  Top 0.406: 9.18,31.8 10.82,31.8 12.14,30.48 | 14.99,22.71 16.41,22.71 16.57,22.71 | 14.99,22.71 14.99,21.92 14.96,21.92 TP16.1 | 14.99,22.71 12.9,22.71 12.14,23.47 12.14,30.48 | U12.1 17.53,33.84 v17.2,33.5 | 12.14,30.48 12.9,30.48 v13.79,31.37
  Bottom 0.406: v17.2,33.5 17.14,33.5 15.01,31.37 v13.79,31.37
VIN2  (via drill 0.36, 0.41)
  Top 0.127: 19.95,14.23 19.96,14.22 19.68,14.22 U10.8
  Top 0.406: 53.91,24.9 v53.91,22.91 | U8.6 U8.7 53.91,24.9 | 53.91,24.9 U8.8 53.95,24.92 C2.1 | v18.36,11.51 v18.37,11.51 U10.6 U10.7 U10.8 C27.1 | C29.1 29.03,14.38 U11.8 U11.7 U11.6 27.56,14.2 v27.56,12.17
  other vias: 22.25,7.92 24.03,7.92 20.47,7.92 25.81,7.92 27.58,7.92 29.36,7.92 23.16,5.23 24.94,5.23 21.39,5.23 26.72,5.23 28.5,5.23 30.28,5.23
  pour Route3 (isolate 0.203, no thermals): 12.75,15.7 69.09,15.7 69.09,0.66 17.88,0.66 17.78,7.8 12.75,7.8
  pour Route3 (isolate 0.203): 44.96,15.7 44.96,26.97 69.09,26.97 69.09,15.7
  pour Top (isolate 0.203, no thermals): 31.45,7.52 34.04,7.52 34.04,5.87 30.89,4.27 20.78,4.27 19.76,5.28 17.93,5.28 17.93,8.89 30.07,8.89
VIN_JACK
  Top 0.127: 57.53,19.02 57.51,19.05 57.48,19.05 | C1.1 58.12,9.55 | 57.3,14.76 57.56,15.01
  Top 0.813: J1.1 57.53,19.02 | 57.56,15.01 57.43,15.14 J1.1 | 58.12,9.55 63.12,14.56 63.12,14.71 63.27,14.71 J2.1 57.3,14.76 F1.1 | TP1.1 52.07,19.02 J1.1

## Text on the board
Top: Top Layer
Route2: Route 2
Route3: Route 3
Bottom: Bottom Layer
tPlace: EVAL-CN0178C-SDP | REVC | +6V | GND | Top Overlay
bPlace: Bottom Overlay
tcourt: Courtyard Top
bcourt: Courtyard Bottom
Fabrication: 1. BOARD TO BE FABRICATED PER IPC-6012A, CLASS 2. | 2. MATERIAL: POLYCLAD FR-370HR OR EQUIVALENT. OUTER LAYERS 1/2 OZ/SQFT | CU INNER LAYERS 1/2 OZ/SQFT CU FINISHED 0.062 | 0.022" +/- 0.003" | (.050 MIN .070 MAX SEE DETAIL). VENDOR MAY ADJUST | THICKNESS TO FULFILL NOTE 9. | 3. PLATING: ADDITIONAL CU PLATING 1 OZ/SQFT | ALL HOLES PLATED THROUGH | MINIMUM PTH BARREL THICKNESS = 0.0008" MINIMUM AVERAGE | PER IPC-6012A WITH AMENDMENT 1, CLASS 2 REQUIREMENTS. | WITH NO SINGLE MEASUREMENT LESS THAN 0.00071 IN THE PLATED HOLES. | 4. FINISH: SURFACES TO BE COATED BY ENIG OF 2 TO 10 MICROINCHES OVER | 15 | A MINIMUM OF 60-200 MICROINCHES OF LOW STRESS NICKEL. | 5. SOLDERMASK: SOLDER MASK TO BE TRANSPARENT GREEN LPI BOTH SIDES PER GERBER FILES. | 6. SILKSCREEN: WHITE EPOXY INK, APPLY TO BOTH SIDES PER GERBER FILES. | 7. ARTWORK: MINIMUM FEATURE SIZE = 0.00492 | MINIMUM AIR GAP = 0.00449 | SCORE DETAIL | 8. ALL DIMENSIONS ARE IN INCHES. | 9. CONTROLLED IMPEDANCE: BOARD TO BE BUILT TO YIELD CONTROLLED IMPEDANCE | 2.75 in. | OF 50 OHMS +/- 10% ON ALL .008" LINE WIDTHS | 10. DO NOT ADD NON-FUNCTIONAL COPPER THIEVING ON OPEN AREAS OF | OUTER LAYERS. THIEVING IS ALLOWED ON INNER LAYERS, UNLESS | OTHERWISE SPECIFIED. | 11. VIAS SHOULD BE COVERED ACCORDING TO ONE OF THE FOLLOWING METHODS. | METHOD 1 IS PREFERRED. | METHOD 1: VIAS MUST BE FILLED WITH SOLDERMASK MATERIAL AFTER | ELECTROLESS NICKEL/IMMERSION GOLD AND BEFORE PRIMARY LPI MASK | AFTER THE FILL IS CURED, THE PRIMARY MASK IS THEN APPLIED WITH NO | VIA APERATURES BOTH SIDES. | METHOD 2: AFTER APPLICATION OF FULL BODY ELECTROLESS | 2.25 in. | NICKEL/IMMERSION GOLD, APPLY PRIMARY LPI MASK WITH REDUCED | VIA APERATURES THAT ARE 6 MILS LARGER THAN DRILLED HOLE DIAMETER | BOTH SIDES. THE APPLY SOLDER MASK PLUG ON COMPONENT SIDE. | 12. TEARDROP PADS ARE ACCEPTABLE WHERE NEEDED. | 13. REMOVAL OF NON-FUNCTIONAL PADS ON LAYERS 1 AND 4 IS ACCEPTABLE | 14. USE IPC-D 356A NETLIST AS SUPPLIED FOR CHECKING. | 15. V SCORE 1 LINE ON BOTH SIDES OF THE BOARD. SEE DETAIL. | 16. ON ALL VIAS LESS THAN OR EQUAL TO 16 MIL'S, PLEASE IGNORE THE STOP MASK AND FILL THE VIA WITH SOLDER MASK AS DICTATED BY NOTE 11 | 17. AFTER FABRICATION PLEASE MILL TWO SLOTS (1.1mmx3mm) AND ONE SLOT(1.1mmx3.5mm) | Fab Drawing | AT THE LOCATIONS SPECIFIED BY THE GERBER MILLING FILE | 4 LAYER CONSTRUCTION DETAIL | SCALE : NONE | UNLESS OTHERWISE SPECIFIED | CONTRACT NO. | 831 Woburn St | ANALOG | Wilmington, MA 01887 | SILKSCREEN | DIMENSIONS ARE IN INCHES | SOLDER MASK | 781-937-2424 | TOLERANCES ARE : | LAYER 1 TOP LAYER | .5 OZ CU. | DEVICES | FAX: 781-937-1021 | LAYER 2 SUPPLY LAYER +5V | .5 OZ CU. | .XX +/- .010 .XXX +/- .005 | APPROVALS | DATE | 0.062" | LAYER 3 SUPPLY LAYER GND | .5 OZ CU. | SEE NOTE 2 | FABRICATION DRAWING | LAYER 4 BOTTOM LAYER | .5 OZ CU. | MATERIAL | DRAWN | SOLDER MASK | NLW | 12/08/10 | CN0178-PCB | SILKSCREEN | SEE NOTES | CHECKED | SIZE | REV. | FINISH | ENGINEERING | DWG. NO. | C | SEE NOTES | QUALITY | B | DO NOT SCALE THIS DRAWING | MANUFACTURING | SCALE | 1:1 | SHEET | 1 | OF | 1
tAsm: 24L3C2A | ADL5902 | ADG3231 | J4 | AD7466 | ADG3231 | ADG3231 | ADP3336 | FX8-120S-SV(21) | ADP3336 | ADP3336 | BNX016-01 | PJ-002A | ADP3336 | Top Assembly
bAsm: Bottom Assembly
DrillLegend: Drill Table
